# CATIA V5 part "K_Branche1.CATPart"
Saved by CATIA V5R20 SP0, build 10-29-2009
Part number: Branche1
Bounding box of the stored display mesh (mm): x 12.5 to 27.5, y 140 to 376.797, z -107.399 to 48.468
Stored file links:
  G:\Khaled_CFAO_2011\SIL\SIL_GR1\mneves\Khaled\CAD_CATIA_Modifie\K_Branche1.CATPart
  G:\Khaled_CFAO_2011\SIL\SIL_GR1\mneves\Khaled\CAD_CATIA_Modifie\K_AssPince_A_Bois.CATProduct
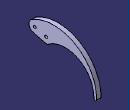
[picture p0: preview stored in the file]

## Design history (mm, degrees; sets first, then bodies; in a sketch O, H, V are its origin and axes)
External parameters (linked from other documents)
  External.Distance_Inter_Pivot = 200 mm
  External.Rayon_Pivot = 5 mm
  External.Epaisseur_Branche = 15 mm
Set1
  Plane1: linked copy from another document
  Point1 "Pivot_Vérin_Branche1": linked copy from another document
  Line1: linked copy from another document
  Point2: linked copy from another document
Body1 (main body)
  Sketch1 on Plane1, origin (12.5, 0, 0), H (0, 1, 0), V (0, 0, 1)
    line L1 (155.1493, -9.4029) -> (203.6564, -21.5296)
    point P2 (203.6564, -21.5296)
    reference projected line E1 (160, 10) -> (200, 0) from Line1
    arc A1 centre (160, 10) radius 20 from (149.7231, 27.1577) to (155.1493, -9.4029) ccw
    point P3 (160, 10)
    reference projected line E2 (160, 10) -> (200, 0) from Line1
    point P4 (149.7231, 27.1577)
    arc A2 centre (226.7999, -101.5247) radius 150 from (149.7231, 27.1577) to (376.7972, -102.4298) cw
    arc A3 centre (371.7973, -102.3997) radius 5 from (376.7972, -102.4298) to (366.7999, -102.2392) cw
    point P7 (371.7973, -102.3997)
    point P8 (366.7999, -102.2392)
    point P9 (366.7999, -102.2392)
    arc A4 centre (266.8514, -99.0306) radius 100 from (366.7999, -102.2392) to (203.6564, -21.5296) ccw
    point P11 (203.6564, -21.5296)
    circle A5 centre (200, 0) radius 5
    point P12 (200, 0)
    circle A6 centre (160, 10) radius 5
    point P13 (160, 10)
    reference projected point E3 (200, 0) from Point2
    reference projected point E4 (200, 0) from Point2
    reference projected point E5 (200, 0) from Point2
    reference projected point E6 (160, 10) from Point1
    reference projected point E7 (160, 10) from Point1
    distance E2 L1 = 20 {= External.Distance_Inter_Pivot /10}
    radius A4 = 100 {= External.Distance_Inter_Pivot /2}
    length L1 = 50 {= External.Distance_Inter_Pivot /4}
    radius A2 = 150 {= External.Distance_Inter_Pivot *(3/4)}
    radius A3 = 5 {= External.Distance_Inter_Pivot /40}
    radius A5 = 5 {= External.Distance_Inter_Pivot /40}
    radius A6 = 5 {= External.Distance_Inter_Pivot /40}
    distance E3 P4 = 57.1429 {= External.Distance_Inter_Pivot /3.5}
    distance P7 E4 = 200 {= External.Distance_Inter_Pivot}
    parallelism: L1 E1
    tangency: L1 A1, A3 A2, A4 A3, A1 A2
    coincidence: P11 L1, P11 P2, P8 P9, P12 E5, P13 E6, P3 E7
  Pad1: profile Sketch1, direction (1, 0, 0), length 15 {= External.Epaisseur_Branche}
  Fillet1: radius 5, on edge [face of Pad1 from Sketch1.A4 | face of Pad1 from Sketch1.L1]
